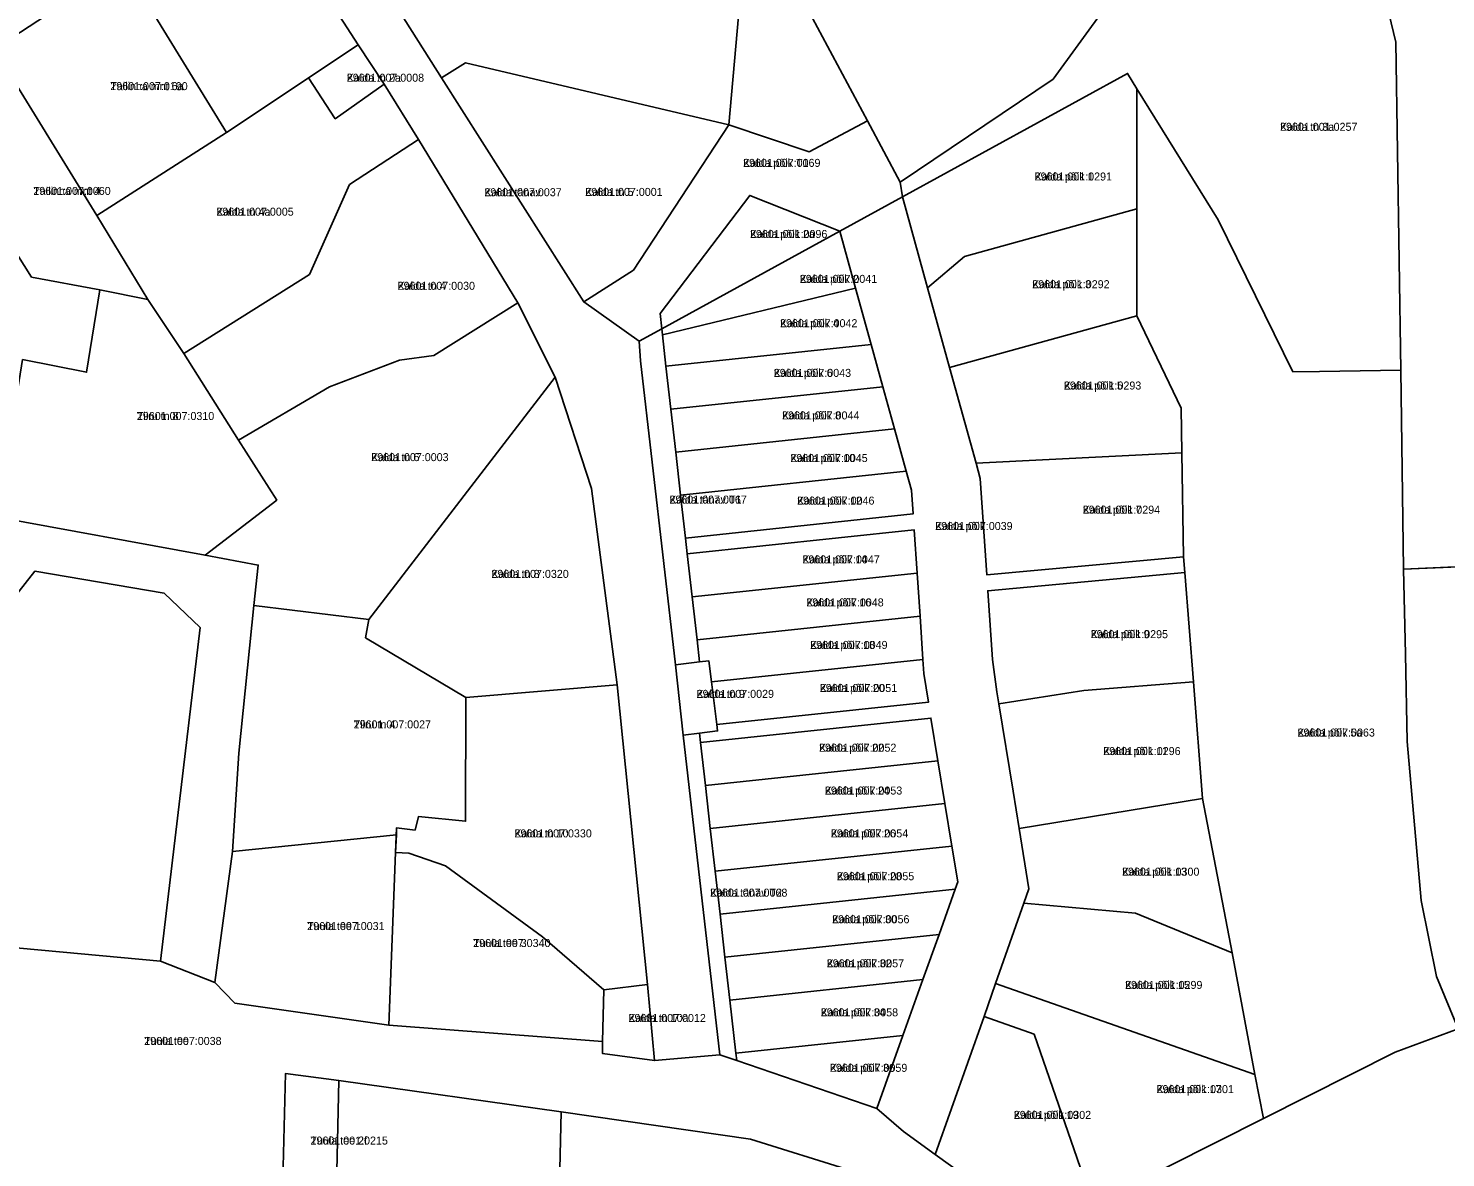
# Model space of a CAD drawing. Extents: x 518839 to 525192, y 6573164 to 6576561.
# Drawn here: x 524522.2 to 524787.8, y 6574409.9 to 6574621.6 of the extents above; entities that cross this region are included whole.
import ezdxf

# ---------------------------------------------------------------- set-up
doc = ezdxf.new("R2010")
doc.units = 0
for name, color, linetype in [('L_AADRESS', 7, 'Continuous'), ('PIIR', 7, 'Continuous'), ('TUNNUS', 7, 'Continuous')]:
    doc.layers.add(name, color=color, linetype=linetype)

msp = doc.modelspace()

# ---------------------------------------------------------------- linework, layer by layer
at = {"layer": 'PIIR'}
for points in [[(524666.82, 6574714.96), (524669.8, 6574716.91), (524686.99, 6574681.78), (524695.3, 6574664.74), (524667.63, 6574644.75), (524664.47, 6574632.29), (524679.45, 6574604.28), (524668.54, 6574598.45), (524653.5, 6574603.51), (524656.89, 6574641.46), (524663.85, 6574658.67), (524687.02, 6574673.75)], [(524667.63, 6574644.75), (524695.3, 6574664.74), (524697.2, 6574663.54), (524734.5, 6574639.94), (524714.3, 6574612.07), (524685.59, 6574592.78), (524679.45, 6574604.28), (524664.47, 6574632.29)], [(524563.49, 6574648.12), (524572.2, 6574654.48), (524591.75, 6574624.76), (524599.66, 6574612.34), (524626.3, 6574570.33), (524636.7, 6574562.97), (524636.94, 6574559.24), (524643.5, 6574502.29), (524644.95, 6574489.1), (524651.82, 6574429.21), (524639.54, 6574428.13), (524638.25, 6574442.35), (524632.55, 6574498.54), (524627.73, 6574535.32), (524620.94, 6574556.2), (524613.94, 6574570.17), (524595.35, 6574600.76), (524588.87, 6574611.12), (524584.04, 6574618.52), (524566.43, 6574645.69)], [(524540.05, 6574633.54), (524563.49, 6574648.12), (524566.43, 6574645.69), (524584.04, 6574618.52), (524559.31, 6574602.05)], [(524622.48, 6574635.23), (524640.19, 6574645.83), (524656.89, 6574641.46), (524653.5, 6574603.51), (524604.13, 6574615.15), (524599.66, 6574612.34), (524591.75, 6574624.76), (524618.28, 6574641.8)], [(524685.59, 6574592.78), (524714.3, 6574612.07), (524734.5, 6574639.94), (524761.87, 6574645.54), (524771.64, 6574647.53), (524778.52, 6574619.01), (524779.42, 6574557.51), (524764.21, 6574557.29), (524759.21, 6574557.22), (524745.18, 6574585.67), (524729.98, 6574610.24), (524728.22, 6574613.15), (524686.03, 6574589.99)], [(524515.81, 6574617.7), (524540.05, 6574633.54), (524559.31, 6574602.05), (524535.06, 6574586.49)], [(524501.66, 6574608.47), (524515.81, 6574617.7), (524535.06, 6574586.49), (524544.6, 6574570.79), (524535.57, 6574572.56), (524522.8, 6574574.95), (524516.96, 6574584.21)], [(524588.87, 6574611.12), (524579.72, 6574604.64), (524574.68, 6574612.32), (524584.04, 6574618.52)], [(524599.66, 6574612.34), (524604.13, 6574615.15), (524653.5, 6574603.51), (524635.63, 6574576.27), (524626.3, 6574570.33)], [(524582.39, 6574592.3), (524574.88, 6574575.44), (524551.37, 6574560.62), (524544.6, 6574570.79), (524535.06, 6574586.49), (524559.31, 6574602.05), (524574.68, 6574612.32), (524579.72, 6574604.64), (524588.87, 6574611.12), (524595.35, 6574600.76)], [(524697.65, 6574578.8), (524690.72, 6574572.98), (524686.03, 6574589.99), (524728.22, 6574613.15), (524729.98, 6574610.24), (524729.97, 6574587.74)], [(524729.95, 6574567.71), (524729.97, 6574587.74), (524729.98, 6574610.24), (524745.18, 6574585.67), (524759.21, 6574557.22), (524764.21, 6574557.29), (524779.42, 6574557.51), (524779.97, 6574520.21), (524780.29, 6574504.31), (524780.62, 6574487.94), (524783.28, 6574458.13), (524786.11, 6574443.88), (524790.19, 6574434.06), (524778.37, 6574429.72), (524753.73, 6574417.26), (524752.09, 6574425.48), (524747.82, 6574448.33), (524742.29, 6574477.22), (524740.6, 6574499.13), (524738.98, 6574519.6), (524738.72, 6574522.55), (524738.4, 6574542.04), (524738.26, 6574550.38)], [(524653.5, 6574603.51), (524668.54, 6574598.45), (524679.45, 6574604.28), (524685.59, 6574592.78), (524686.03, 6574589.99), (524674.3, 6574583.58), (524657.4, 6574590.26), (524640.6, 6574568.11), (524640.92, 6574565.28), (524636.7, 6574562.97), (524626.3, 6574570.33), (524635.63, 6574576.27)], [(524613.94, 6574570.17), (524598.21, 6574560.24), (524591.75, 6574559.37), (524578.62, 6574554.41), (524561.57, 6574544.39), (524551.37, 6574560.62), (524574.88, 6574575.44), (524582.39, 6574592.3), (524595.35, 6574600.76)], [(524640.6, 6574568.11), (524657.4, 6574590.26), (524674.3, 6574583.58), (524640.92, 6574565.28)], [(524680.18, 6574562.33), (524677.26, 6574572.9), (524674.3, 6574583.58), (524686.03, 6574589.99), (524690.72, 6574572.98), (524694.85, 6574558.02), (524699.82, 6574540.07), (524700.6, 6574537.23), (524701.83, 6574519.19), (524738.72, 6574522.55), (524738.98, 6574519.6), (524702.03, 6574516.19), (524702.93, 6574503.32), (524703.75, 6574497.26), (524704.11, 6574494.99), (524706.76, 6574478.59), (524707.89, 6574471.64), (524709.71, 6574460.3), (524708.78, 6574457.62), (524703.48, 6574442.58), (524701.35, 6574436.41), (524692.17, 6574410.53), (524686.25, 6574414.8), (524681.23, 6574419.16), (524686.13, 6574432.85), (524689.86, 6574443.29), (524692.89, 6574451.75), (524695.92, 6574460.22), (524696.41, 6574461.59), (524695.29, 6574468.3), (524693.96, 6574476.3), (524692.67, 6574484.31), (524691.37, 6574492.32), (524648.19, 6574487.74), (524647.99, 6574489.48), (524651.39, 6574489.91), (524651.24, 6574491.08), (524690.9, 6574495.29), (524690.06, 6574500.65), (524689.88, 6574503.32), (524689.33, 6574511.41), (524688.78, 6574519.5), (524688.24, 6574527.59), (524645.7, 6574523.07), (524645.36, 6574526.05), (524688.03, 6574530.58), (524687.73, 6574535.04), (524686.75, 6574538.59), (524684.56, 6574546.5), (524682.37, 6574554.42)], [(524894.07, 6574590.88), (524900.39, 6574574.13), (524866.42, 6574559.71), (524834.46, 6574537.36), (524835.21, 6574509.37), (524807.21, 6574501.9), (524799.66, 6574499.88), (524817.51, 6574442.43), (524790.19, 6574434.06), (524786.11, 6574443.88), (524783.28, 6574458.13), (524780.62, 6574487.94), (524780.29, 6574504.31), (524779.97, 6574520.21), (524800.71, 6574521.13), (524826.31, 6574548.47), (524851.12, 6574574.95)], [(524729.95, 6574567.71), (524694.85, 6574558.02), (524690.72, 6574572.98), (524697.65, 6574578.8), (524729.97, 6574587.74)], [(524460.17, 6574547.21), (524476.63, 6574557.88), (524497.1, 6574571.15), (524512.72, 6574581.27), (524516.96, 6574584.21), (524522.8, 6574574.95), (524535.57, 6574572.56), (524533.12, 6574557.13), (524521.11, 6574559.5), (524516.34, 6574529.97), (524464.93, 6574539.89)], [(524640.92, 6574565.28), (524674.3, 6574583.58), (524677.26, 6574572.9), (524641.04, 6574564.17)], [(524521.11, 6574559.5), (524533.12, 6574557.13), (524535.57, 6574572.56), (524544.6, 6574570.79), (524551.37, 6574560.62), (524561.57, 6574544.39), (524568.74, 6574533.17), (524555.31, 6574522.82), (524516.34, 6574529.97)], [(524641.04, 6574564.17), (524677.26, 6574572.9), (524680.18, 6574562.33), (524641.71, 6574558.25)], [(524564.47, 6574513.44), (524565.29, 6574520.99), (524555.31, 6574522.82), (524568.74, 6574533.17), (524561.57, 6574544.39), (524578.62, 6574554.41), (524591.75, 6574559.37), (524598.21, 6574560.24), (524613.94, 6574570.17), (524620.94, 6574556.2), (524586.02, 6574510.76)], [(524738.4, 6574542.04), (524699.82, 6574540.07), (524694.85, 6574558.02), (524729.95, 6574567.71), (524738.26, 6574550.38)], [(524636.7, 6574562.97), (524640.92, 6574565.28), (524641.04, 6574564.17), (524641.71, 6574558.25), (524642.63, 6574550.2), (524643.54, 6574542.15), (524644.45, 6574534.1), (524645.36, 6574526.05), (524645.7, 6574523.07), (524646.61, 6574515.02), (524647.53, 6574506.98), (524647.99, 6574502.85), (524643.5, 6574502.29), (524636.94, 6574559.24)], [(524401.81, 6574532.13), (524431.89, 6574562.69), (524434.43, 6574559.64), (524457.58, 6574545.58), (524460.17, 6574547.21), (524464.93, 6574539.89), (524516.34, 6574529.97), (524555.31, 6574522.82), (524565.29, 6574520.99), (524564.47, 6574513.44), (524561.67, 6574485.75), (524560.44, 6574467.33), (524557.14, 6574442.73), (524546.99, 6574446.75), (524554.43, 6574509.27), (524547.65, 6574515.75), (524523.42, 6574519.87), (524516.79, 6574511.45)], [(524641.71, 6574558.25), (524680.18, 6574562.33), (524682.37, 6574554.42), (524642.63, 6574550.2)], [(524627.73, 6574535.32), (524632.55, 6574498.54), (524604.22, 6574496.14), (524585.41, 6574507.36), (524586.02, 6574510.76), (524620.94, 6574556.2)], [(524642.63, 6574550.2), (524682.37, 6574554.42), (524684.56, 6574546.5), (524643.54, 6574542.15)], [(524643.54, 6574542.15), (524684.56, 6574546.5), (524686.75, 6574538.59), (524644.45, 6574534.1)], [(524738.72, 6574522.55), (524701.83, 6574519.19), (524700.6, 6574537.23), (524699.82, 6574540.07), (524738.4, 6574542.04)], [(524644.45, 6574534.1), (524686.75, 6574538.59), (524687.73, 6574535.04), (524688.03, 6574530.58), (524645.36, 6574526.05)], [(524401.81, 6574532.13), (524516.79, 6574511.45), (524523.42, 6574519.87), (524547.65, 6574515.75), (524554.43, 6574509.27), (524546.99, 6574446.75), (524456.99, 6574455.07), (524385.14, 6574469.23)], [(524645.7, 6574523.07), (524688.24, 6574527.59), (524688.78, 6574519.5), (524646.61, 6574515.02)], [(524646.61, 6574515.02), (524688.78, 6574519.5), (524689.33, 6574511.41), (524647.53, 6574506.98)], [(524720.01, 6574497.5), (524704.11, 6574494.99), (524703.75, 6574497.26), (524702.93, 6574503.32), (524702.03, 6574516.19), (524738.98, 6574519.6), (524740.6, 6574499.13)], [(524564.47, 6574513.44), (524586.02, 6574510.76), (524585.41, 6574507.36), (524604.22, 6574496.14), (524604.14, 6574472.97), (524595.34, 6574473.87), (524594.67, 6574471.31), (524591.22, 6574471.77), (524591.17, 6574470.4), (524560.44, 6574467.33), (524561.67, 6574485.75)], [(524647.53, 6574506.98), (524689.33, 6574511.41), (524689.88, 6574503.32), (524650.23, 6574499.12), (524649.73, 6574503.07), (524647.99, 6574502.85)], [(524643.5, 6574502.29), (524647.99, 6574502.85), (524649.73, 6574503.07), (524650.23, 6574499.12), (524651.24, 6574491.08), (524651.39, 6574489.91), (524647.99, 6574489.48), (524644.95, 6574489.1)], [(524650.23, 6574499.12), (524689.88, 6574503.32), (524690.06, 6574500.65), (524690.9, 6574495.29), (524651.24, 6574491.08)], [(524593.52, 6574467.01), (524591.04, 6574467.11), (524591.22, 6574471.77), (524594.67, 6574471.31), (524595.34, 6574473.87), (524604.14, 6574472.97), (524604.22, 6574496.14), (524632.55, 6574498.54), (524638.25, 6574442.35), (524630.07, 6574441.36), (524618.59, 6574451.31), (524600.4, 6574464.64)], [(524742.29, 6574477.22), (524707.89, 6574471.64), (524706.76, 6574478.59), (524704.11, 6574494.99), (524720.01, 6574497.5), (524740.6, 6574499.13)], [(524648.19, 6574487.74), (524691.37, 6574492.32), (524692.67, 6574484.31), (524649.1, 6574479.69)], [(524644.95, 6574489.1), (524647.99, 6574489.48), (524648.19, 6574487.74), (524649.1, 6574479.69), (524650.02, 6574471.64), (524650.93, 6574463.59), (524651.85, 6574455.54), (524652.76, 6574447.5), (524653.67, 6574439.45), (524654.8, 6574429.53), (524654.96, 6574428.14), (524651.82, 6574429.21)], [(524649.1, 6574479.69), (524692.67, 6574484.31), (524693.96, 6574476.3), (524650.02, 6574471.64)], [(524650.02, 6574471.64), (524693.96, 6574476.3), (524695.29, 6574468.3), (524650.93, 6574463.59)], [(524729.73, 6574455.77), (524708.78, 6574457.62), (524709.71, 6574460.3), (524707.89, 6574471.64), (524742.29, 6574477.22), (524747.82, 6574448.33)], [(524560.44, 6574467.33), (524591.17, 6574470.4), (524591.04, 6574467.11), (524589.76, 6574434.76), (524560.93, 6574438.85), (524557.14, 6574442.73)], [(524650.93, 6574463.59), (524695.29, 6574468.3), (524696.41, 6574461.59), (524695.92, 6574460.22), (524651.85, 6574455.54)], [(524593.52, 6574467.01), (524600.4, 6574464.64), (524618.59, 6574451.31), (524630.07, 6574441.36), (524629.84, 6574431.7), (524589.76, 6574434.76), (524591.04, 6574467.11)], [(524651.85, 6574455.54), (524695.92, 6574460.22), (524692.89, 6574451.75), (524652.76, 6574447.5)], [(524752.09, 6574425.48), (524703.48, 6574442.58), (524708.78, 6574457.62), (524729.73, 6574455.77), (524747.82, 6574448.33)], [(524652.76, 6574447.5), (524692.89, 6574451.75), (524689.86, 6574443.29), (524653.67, 6574439.45)], [(524638.25, 6574442.35), (524639.54, 6574428.13), (524629.82, 6574429.43), (524629.84, 6574431.7), (524630.07, 6574441.36)], [(524653.67, 6574439.45), (524689.86, 6574443.29), (524686.13, 6574432.85), (524654.8, 6574429.53)], [(524710.7, 6574433.06), (524701.35, 6574436.41), (524703.48, 6574442.58), (524752.09, 6574425.48), (524753.73, 6574417.26), (524735.93, 6574408.31), (524721.62, 6574401.47)], [(524711.59, 6574396.58), (524692.17, 6574410.53), (524701.35, 6574436.41), (524710.7, 6574433.06), (524721.62, 6574401.47)], [(524654.8, 6574429.53), (524686.13, 6574432.85), (524681.23, 6574419.16), (524654.96, 6574428.14)], [(524569.76, 6574400.68), (524570.37, 6574425.69), (524580.41, 6574424.36), (524579.81, 6574398.82)], [(524578.79, 6574355.29), (524579.81, 6574398.82), (524580.41, 6574424.36), (524622.07, 6574418.51), (524621.56, 6574397.04), (524622.34, 6574364.41)], [(524676.36, 6574407.54), (524700.15, 6574392.87), (524674.19, 6574379.29), (524674.63, 6574378.38), (524671.89, 6574377.53), (524622.34, 6574364.41), (524621.56, 6574397.04), (524622.07, 6574418.51), (524657.52, 6574413.39)]]:
    msp.add_lwpolyline(points, close=True, dxfattribs=at)
for points in [[(524800.69, 6574521.12), (524779.97, 6574520.21), (524779.42, 6574557.51), (524778.52, 6574619.01), (524771.64, 6574647.53), (524769.98, 6574653.34), (524778.82, 6574656.87), (524833.42, 6574678.59)], [(524456.99, 6574455.07), (524546.99, 6574446.75), (524557.14, 6574442.73), (524560.93, 6574438.85), (524589.76, 6574434.76), (524629.84, 6574431.7), (524629.82, 6574429.43), (524639.54, 6574428.13), (524651.82, 6574429.21), (524654.96, 6574428.14), (524681.23, 6574419.16), (524686.25, 6574414.8), (524692.17, 6574410.53), (524711.59, 6574396.58)], [(524377.78, 6574286.88), (524374.42, 6574333.78), (524391.22, 6574334.37), (524426.7, 6574335.33), (524449.29, 6574335.16), (524459.67, 6574335.09), (524482.48, 6574337.78), (524490.84, 6574339.28), (524518.51, 6574344.28), (524546.14, 6574349.24), (524578.79, 6574355.29), (524622.34, 6574364.41), (524671.89, 6574377.53), (524674.63, 6574378.38), (524674.19, 6574379.29), (524700.15, 6574392.87), (524710.26, 6574396.01), (524711.59, 6574396.58), (524721.62, 6574401.47), (524735.93, 6574408.31), (524753.73, 6574417.26), (524778.37, 6574429.72), (524790.19, 6574434.06)], [(524676.36, 6574407.54), (524657.52, 6574413.39), (524622.07, 6574418.51), (524580.41, 6574424.36), (524570.37, 6574425.69), (524569.76, 6574400.68)]]:
    msp.add_lwpolyline(points, dxfattribs=at)

# ---------------------------------------------------------------- texts
at = {"layer": 'L_AADRESS'}
for s, p in [('Tallinna mnt 6a', (524537.56, 6574610)), ('Kalda tn 2a', (524581.87, 6574611.58)), ('Kalda tn 3a', (524756.8, 6574602.38)), ('Kalda põik T1', (524656.16, 6574595.62)), ('Kalda põik 1', (524710.8, 6574593.07)), ('Tallinna mnt 4', (524523.13, 6574590.36)), ('Kalda tänav', (524607.66, 6574590.12)), ('Kalda tn 5', (524626.58, 6574590.18)), ('Kalda tn 4a', (524557.43, 6574586.47)), ('Kalda põik 2a', (524657.45, 6574582.29)), ('Kalda tn 4', (524591.41, 6574572.58)), ('Kalda põik 2', (524666.79, 6574573.88)), ('Kalda põik 3', (524710.35, 6574572.88)), ('Kalda põik 4', (524663.08, 6574565.57)), ('Kalda põik 6', (524661.9, 6574556.26)), ('Kalda põik 5', (524716.29, 6574553.89)), ('Tiiru tn 8', (524542.54, 6574548.18)), ('Kalda põik 8', (524663.46, 6574548.29)), ('Kalda tn 6', (524586.46, 6574540.47)), ('Kalda põik 10', (524665.01, 6574540.3)), ('Kalda tänav T1', (524642.35, 6574532.51)), ('Kalda põik 12', (524666.28, 6574532.32)), ('Kalda põik 7', (524719.82, 6574530.62)), ('Kalda põik', (524692.17, 6574527.56)), ('Kalda põik 14', (524667.28, 6574521.3)), ('Kalda tn 8', (524608.98, 6574518.59)), ('Kalda põik 16', (524668.01, 6574513.24)), ('Kalda põik 9', (524721.3, 6574507.29)), ('Kalda põik 18', (524668.73, 6574505.27)), ('Kalda tn 9', (524647.45, 6574496.1)), ('Kalda põik 20', (524670.54, 6574497.2)), ('Tiiru tn 4', (524583.17, 6574490.38)), ('Kalda põik 5a', (524760.07, 6574488.85)), ('Kalda põik 22', (524670.39, 6574486.01)), ('Kalda põik 11', (524723.66, 6574485.38)), ('Kalda põik 24', (524671.49, 6574477.98)), ('Kalda tn 10', (524613.3, 6574469.95)), ('Kalda põik 26', (524672.61, 6574469.95)), ('Kalda põik 28', (524673.74, 6574461.92)), ('Kalda põik 13', (524727.18, 6574462.77)), ('Kalda tänav T2', (524649.96, 6574458.84)), ('Kalda põik 30', (524672.84, 6574453.86)), ('Tuula tee 1', (524574.46, 6574452.58)), ('Tuula tee 3', (524605.56, 6574449.4)), ('Kalda põik 32', (524671.83, 6574445.6)), ('Kalda põik 15', (524727.75, 6574441.55)), ('Kalda tn 10a', (524634.68, 6574435.35)), ('Kalda põik 34', (524670.71, 6574436.41)), ('Tuula tee', (524543.91, 6574431.05)), ('Kalda põik 36', (524672.44, 6574426.01)), ('Kalda põik 17', (524733.65, 6574422.02)), ('Kalda põik 19', (524706.89, 6574417.19)), ('Tuula tee 2f', (524575.08, 6574412.38))]:
    msp.add_text(s, height=1.5, dxfattribs=at).set_placement(p)
at = {"layer": 'TUNNUS'}
for s, p in [('29601:007:0190', (524537.56, 6574610)), ('29601:007:0008', (524581.87, 6574611.58)), ('29601:001:0257', (524756.8, 6574602.38)), ('29601:007:0069', (524656.16, 6574595.62)), ('29601:001:0291', (524710.8, 6574593.07)), ('29601:007:0060', (524523.13, 6574590.36)), ('29601:007:0037', (524607.66, 6574590.12)), ('29601:007:0001', (524626.58, 6574590.18)), ('29601:007:0005', (524557.43, 6574586.47)), ('29601:001:0096', (524657.45, 6574582.29)), ('29601:007:0030', (524591.41, 6574572.58)), ('29601:007:0041', (524666.79, 6574573.88)), ('29601:001:0292', (524710.35, 6574572.88)), ('29601:007:0042', (524663.08, 6574565.57)), ('29601:007:0043', (524661.9, 6574556.26)), ('29601:001:0293', (524716.29, 6574553.89)), ('29601:007:0310', (524542.54, 6574548.18)), ('29601:007:0044', (524663.46, 6574548.29)), ('29601:007:0003', (524586.46, 6574540.47)), ('29601:007:0045', (524665.01, 6574540.3)), ('29601:007:0067', (524642.35, 6574532.51)), ('29601:007:0046', (524666.28, 6574532.32)), ('29601:001:0294', (524719.82, 6574530.62)), ('29601:007:0039', (524692.17, 6574527.56)), ('29601:007:0047', (524667.28, 6574521.3)), ('29601:007:0320', (524608.98, 6574518.59)), ('29601:007:0048', (524668.01, 6574513.24)), ('29601:001:0295', (524721.3, 6574507.29)), ('29601:007:0049', (524668.73, 6574505.27)), ('29601:007:0029', (524647.45, 6574496.1)), ('29601:007:0051', (524670.54, 6574497.2)), ('29601:007:0027', (524583.17, 6574490.38)), ('29601:007:0063', (524760.07, 6574488.85)), ('29601:007:0052', (524670.39, 6574486.01)), ('29601:001:0296', (524723.66, 6574485.38)), ('29601:007:0053', (524671.49, 6574477.98)), ('29601:007:0330', (524613.3, 6574469.95)), ('29601:007:0054', (524672.61, 6574469.95)), ('29601:007:0055', (524673.74, 6574461.92)), ('29601:001:0300', (524727.18, 6574462.77)), ('29601:007:0068', (524649.96, 6574458.84)), ('29601:007:0056', (524672.84, 6574453.86)), ('29601:007:0031', (524574.46, 6574452.58)), ('29601:007:0340', (524605.56, 6574449.4)), ('29601:007:0057', (524671.83, 6574445.6)), ('29601:001:0299', (524727.75, 6574441.55)), ('29601:007:0012', (524634.68, 6574435.35)), ('29601:007:0058', (524670.71, 6574436.41)), ('29601:007:0038', (524543.91, 6574431.05)), ('29601:007:0059', (524672.44, 6574426.01)), ('29601:001:0301', (524733.65, 6574422.02)), ('29601:001:0302', (524706.89, 6574417.19)), ('29601:001:0215', (524575.08, 6574412.38))]:
    msp.add_text(s, height=1.5, dxfattribs=at).set_placement(p)

doc.saveas('drawing.dxf')
